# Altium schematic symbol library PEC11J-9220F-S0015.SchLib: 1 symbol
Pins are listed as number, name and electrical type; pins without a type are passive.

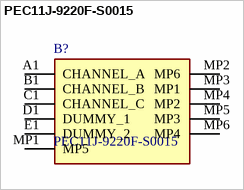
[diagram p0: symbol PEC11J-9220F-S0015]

## PEC11J-9220F-S0015
designator B?
12 mm SMD Long Life Encoder; Manufacturer_Name: Bourns; Geometry.Height: 25mm
footprint PEC11J9220FS0015
pins: A1 CHANNEL_A, B1 CHANNEL_B, C1 CHANNEL_C, D1 DUMMY_1, E1 DUMMY_2, MP1 MP5, MP2 MP6, MP3 MP1, MP4 MP2, MP5 MP3, MP6 MP4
